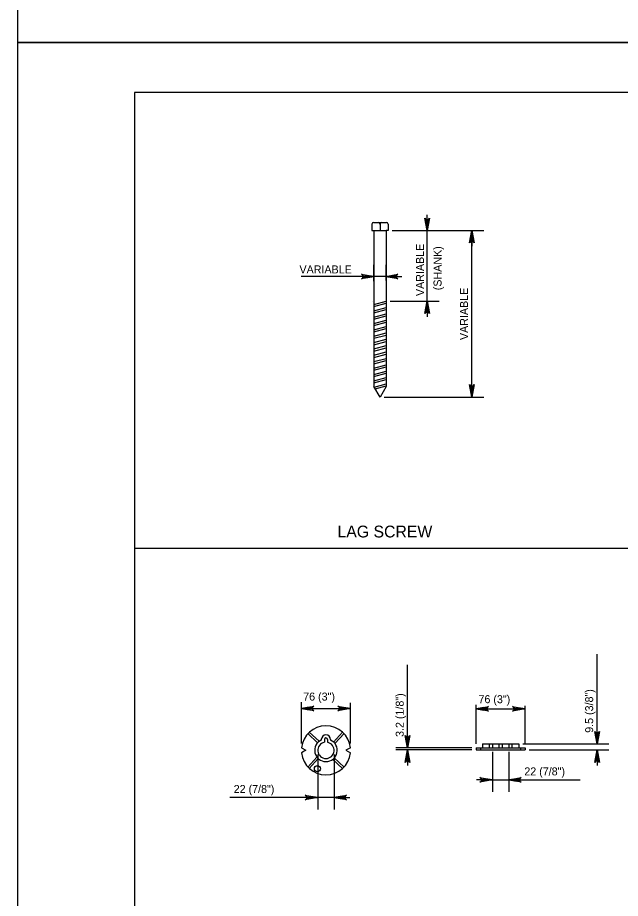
# Model space of a CAD drawing. Extents: x 0 to 36.3, y -66 to 0.
# Drawn here: x 0 to 9.04, y -56.84 to -43.62 of the extents above; entities that cross this region are included whole.
import ezdxf

# ---------------------------------------------------------------- set-up
doc = ezdxf.new("R2010")
doc.units = 0
for name, color, linetype in [('1', 7, 'Continuous'), ('3', 7, 'Continuous'), ('4', 7, 'Continuous'), ('5', 7, 'Continuous'), ('62', 7, 'Continuous'), ('63', 7, 'Continuous')]:
    doc.layers.add(name, color=color, linetype=linetype)

msp = doc.modelspace()

# ---------------------------------------------------------------- linework, layer by layer
at = {"layer": '1'}
msp.add_lwpolyline([(1.75, -65.25), (33.25, -65.25), (33.25, -44.75), (1.75, -44.75)], close=True, dxfattribs=at)
at = {"layer": '3'}
for p, q in [((5.617, -46.819), (6.989, -46.819)), ((6.811, -49.316), (6.811, -46.819)), ((6.811, -46.819), (6.811, -46.819)), ((6.811, -46.937), (6.811, -47.055)), ((5.34, -47.576), (5.34, -47.333)), ((5.525, -47.568), (5.525, -47.333)), ((5.222, -47.51), (4.252, -47.51)), ((5.525, -47.51), (5.34, -47.51)), ((5.643, -47.51), (5.761, -47.51)), ((5.494, -49.316), (6.989, -49.316)), ((1.75, -51.583), (32.25, -51.583)), ((8.687, -54.28), (8.687, -53.172)), ((5.847, -54.341), (5.847, -53.332)), ((4.254, -54.514), (4.254, -53.895)), ((4.373, -53.987), (4.87, -53.987)), ((4.989, -54.514), (4.989, -53.904)), ((4.989, -53.987), (4.989, -53.987)), ((6.873, -54.516), (6.873, -53.934)), ((6.991, -53.994), (7.489, -53.994)), ((7.607, -54.516), (7.607, -53.946)), ((7.607, -53.994), (7.607, -53.994)), ((8.687, -54.398), (8.687, -54.28)), ((5.847, -54.459), (5.847, -54.341)), ((7.573, -54.516), (8.864, -54.516)), ((8.687, -54.516), (8.687, -54.516)), ((4.499, -54.676), (4.499, -55.501)), ((4.745, -54.676), (4.745, -55.501)), ((6.811, -54.578), (5.67, -54.578)), ((6.811, -54.608), (5.67, -54.608)), ((5.847, -54.578), (5.847, -54.578)), ((7.117, -54.639), (7.117, -55.236)), ((7.363, -54.639), (7.363, -55.236)), ((7.668, -54.608), (8.864, -54.608)), ((5.847, -54.726), (5.847, -54.844)), ((8.687, -54.726), (8.687, -54.844)), ((6.998, -55.059), (6.88, -55.059)), ((7.117, -55.059), (8.432, -55.059)), ((7.363, -55.059), (7.363, -55.059)), ((7.481, -55.059), (7.599, -55.059)), ((4.745, -55.324), (3.181, -55.324)), ((4.38, -55.324), (4.447, -55.324)), ((4.863, -55.324), (4.981, -55.324))]:
    msp.add_line(p, q, dxfattribs=at)
for points in [[(6.14, -46.819), (6.105, -46.632), (6.115, -46.647), (6.128, -46.654), (6.14, -46.656), (6.153, -46.654), (6.165, -46.647), (6.175, -46.632), (6.14, -46.819), (6.165, -46.647), (6.153, -46.654), (6.14, -46.819), (6.14, -46.656), (6.128, -46.654), (6.14, -46.819), (6.115, -46.647)], [(6.811, -46.819), (6.846, -47.005), (6.836, -46.991), (6.824, -46.983), (6.811, -46.981), (6.799, -46.983), (6.786, -46.991), (6.776, -47.005), (6.811, -46.819), (6.786, -46.991), (6.799, -46.983), (6.811, -46.819), (6.811, -46.981), (6.824, -46.983), (6.811, -46.819), (6.836, -46.991)], [(5.34, -47.51), (5.154, -47.545), (5.168, -47.535), (5.175, -47.523), (5.178, -47.51), (5.175, -47.498), (5.168, -47.485), (5.154, -47.475), (5.34, -47.51), (5.168, -47.485), (5.175, -47.498), (5.34, -47.51), (5.178, -47.51), (5.175, -47.523), (5.34, -47.51), (5.168, -47.535)], [(5.514, -47.51), (5.701, -47.475), (5.686, -47.485), (5.679, -47.498), (5.677, -47.51), (5.679, -47.523), (5.686, -47.535), (5.701, -47.545), (5.514, -47.51), (5.686, -47.535), (5.679, -47.523), (5.514, -47.51), (5.677, -47.51), (5.679, -47.498), (5.514, -47.51), (5.686, -47.485)], [(6.14, -47.876), (6.175, -48.063), (6.165, -48.048), (6.153, -48.041), (6.14, -48.039), (6.128, -48.041), (6.115, -48.048), (6.105, -48.063), (6.14, -47.876), (6.115, -48.048), (6.128, -48.041), (6.14, -47.876), (6.14, -48.039), (6.153, -48.041), (6.14, -47.876), (6.165, -48.048)], [(6.811, -49.316), (6.776, -49.13), (6.786, -49.144), (6.799, -49.152), (6.811, -49.154), (6.824, -49.152), (6.836, -49.144), (6.846, -49.13), (6.811, -49.316), (6.836, -49.144), (6.824, -49.152), (6.811, -49.316), (6.811, -49.154), (6.799, -49.152), (6.811, -49.316), (6.786, -49.144)], [(4.255, -53.987), (4.441, -53.952), (4.427, -53.962), (4.419, -53.974), (4.417, -53.987), (4.419, -53.999), (4.427, -54.012), (4.441, -54.021), (4.255, -53.987), (4.427, -54.012), (4.419, -53.999), (4.255, -53.987), (4.417, -53.987), (4.419, -53.974), (4.255, -53.987), (4.427, -53.962)], [(4.989, -53.987), (4.802, -54.021), (4.817, -54.012), (4.824, -53.999), (4.826, -53.987), (4.824, -53.974), (4.817, -53.962), (4.802, -53.952), (4.989, -53.987), (4.817, -53.962), (4.824, -53.974), (4.989, -53.987), (4.826, -53.987), (4.824, -53.999), (4.989, -53.987), (4.817, -54.012)], [(6.873, -53.994), (7.059, -53.959), (7.045, -53.969), (7.037, -53.981), (7.035, -53.994), (7.037, -54.006), (7.045, -54.019), (7.059, -54.029), (6.873, -53.994), (7.045, -54.019), (7.037, -54.006), (6.873, -53.994), (7.035, -53.994), (7.037, -53.981), (6.873, -53.994), (7.045, -53.969)], [(7.607, -53.994), (7.42, -54.029), (7.435, -54.019), (7.442, -54.006), (7.444, -53.994), (7.442, -53.981), (7.435, -53.969), (7.42, -53.959), (7.607, -53.994), (7.435, -53.969), (7.442, -53.981), (7.607, -53.994), (7.444, -53.994), (7.442, -54.006), (7.607, -53.994), (7.435, -54.019)], [(5.847, -54.578), (5.812, -54.391), (5.822, -54.405), (5.835, -54.413), (5.847, -54.415), (5.86, -54.413), (5.872, -54.405), (5.882, -54.391), (5.847, -54.578), (5.872, -54.405), (5.86, -54.413), (5.847, -54.578), (5.847, -54.415), (5.835, -54.413), (5.847, -54.578), (5.822, -54.405)], [(8.687, -54.516), (8.652, -54.33), (8.662, -54.344), (8.674, -54.351), (8.687, -54.353), (8.699, -54.351), (8.712, -54.344), (8.722, -54.33), (8.687, -54.516), (8.712, -54.344), (8.699, -54.351), (8.687, -54.516), (8.687, -54.353), (8.674, -54.351), (8.687, -54.516), (8.662, -54.344)], [(5.847, -54.608), (5.882, -54.795), (5.872, -54.78), (5.86, -54.773), (5.847, -54.771), (5.835, -54.773), (5.822, -54.78), (5.812, -54.795), (5.847, -54.608), (5.822, -54.78), (5.835, -54.773), (5.847, -54.608), (5.847, -54.771), (5.86, -54.773), (5.847, -54.608), (5.872, -54.78)], [(8.687, -54.608), (8.722, -54.795), (8.712, -54.78), (8.699, -54.773), (8.687, -54.771), (8.674, -54.773), (8.662, -54.78), (8.652, -54.795), (8.687, -54.608), (8.662, -54.78), (8.674, -54.773), (8.687, -54.608), (8.687, -54.771), (8.699, -54.773), (8.687, -54.608), (8.712, -54.78)], [(7.117, -55.059), (6.93, -55.094), (6.944, -55.084), (6.952, -55.072), (6.954, -55.059), (6.952, -55.047), (6.944, -55.034), (6.93, -55.024), (7.117, -55.059), (6.944, -55.034), (6.952, -55.047), (7.117, -55.059), (6.954, -55.059), (6.952, -55.072), (7.117, -55.059), (6.944, -55.084)], [(7.363, -55.059), (7.549, -55.024), (7.535, -55.034), (7.527, -55.047), (7.525, -55.059), (7.527, -55.072), (7.535, -55.084), (7.549, -55.094), (7.363, -55.059), (7.535, -55.084), (7.527, -55.072), (7.363, -55.059), (7.525, -55.059), (7.527, -55.047), (7.363, -55.059), (7.535, -55.034)], [(4.499, -55.324), (4.312, -55.358), (4.327, -55.349), (4.334, -55.336), (4.336, -55.324), (4.334, -55.311), (4.327, -55.299), (4.312, -55.289), (4.499, -55.324), (4.327, -55.299), (4.334, -55.311), (4.499, -55.324), (4.336, -55.324), (4.334, -55.336), (4.499, -55.324), (4.327, -55.349)], [(4.745, -55.324), (4.931, -55.289), (4.917, -55.299), (4.909, -55.311), (4.907, -55.324), (4.909, -55.336), (4.917, -55.349), (4.931, -55.358), (4.745, -55.324), (4.917, -55.349), (4.909, -55.336), (4.745, -55.324), (4.907, -55.324), (4.909, -55.311), (4.745, -55.324), (4.917, -55.299)]]:
    msp.add_lwpolyline(points, dxfattribs=at)
for points in [[(6.831, -46.937), (6.792, -46.937), (6.811, -46.819)], [(5.222, -47.491), (5.222, -47.53), (5.34, -47.51)], [(5.643, -47.491), (5.643, -47.53), (5.525, -47.51)], [(6.831, -49.198), (6.792, -49.198), (6.811, -49.316)], [(4.373, -54.006), (4.373, -53.967), (4.255, -53.987)], [(4.87, -54.006), (4.87, -53.967), (4.989, -53.987)], [(6.991, -54.014), (6.991, -53.974), (6.873, -53.994)], [(7.489, -54.014), (7.489, -53.974), (7.607, -53.994)], [(8.707, -54.398), (8.667, -54.398), (8.687, -54.516)], [(5.867, -54.459), (5.828, -54.459), (5.847, -54.578)], [(5.867, -54.726), (5.828, -54.726), (5.847, -54.608)], [(8.707, -54.726), (8.667, -54.726), (8.687, -54.608)], [(6.998, -55.079), (6.998, -55.04), (7.117, -55.059)], [(7.481, -55.079), (7.481, -55.04), (7.363, -55.059)], [(4.38, -55.343), (4.38, -55.304), (4.499, -55.324)], [(4.863, -55.343), (4.863, -55.304), (4.745, -55.324)]]:
    msp.add_lwpolyline(points, close=True, dxfattribs=at)
at = {"layer": '4'}
for p, q in [((6.14, -46.701), (6.14, -46.583)), ((5.309, -46.723), (5.309, -46.819)), ((5.309, -46.723), (5.309, -46.723)), ((5.337, -46.696), (5.405, -46.696)), ((5.405, -46.696), (5.528, -46.696)), ((5.433, -46.723), (5.433, -46.819)), ((5.555, -46.723), (5.555, -46.819)), ((5.555, -46.723), (5.555, -46.723)), ((5.309, -46.819), (5.34, -46.819)), ((5.34, -46.819), (5.34, -47.865)), ((5.34, -46.819), (5.525, -46.819)), ((5.525, -46.819), (5.525, -47.865)), ((5.555, -46.819), (5.525, -46.819)), ((5.555, -46.819), (5.555, -46.819)), ((5.846, -46.819), (6.317, -46.819)), ((6.14, -47.876), (6.14, -46.819)), ((5.323, -47.884), (5.323, -47.884)), ((5.34, -47.865), (5.34, -49.157)), ((5.525, -47.865), (5.525, -49.157)), ((5.586, -47.876), (6.317, -47.876)), ((6.14, -47.994), (6.14, -48.112)), ((5.433, -49.316), (5.433, -49.316)), ((4.497, -54.5), (4.35, -54.364)), ((4.52, -54.479), (4.371, -54.341)), ((4.736, -54.49), (4.872, -54.343)), ((4.757, -54.513), (4.895, -54.364)), ((4.552, -54.453), (4.552, -54.46)), ((4.598, -54.453), (4.598, -54.494)), ((4.645, -54.453), (4.645, -54.494)), ((4.691, -54.453), (4.691, -54.46)), ((6.967, -54.516), (6.967, -54.578)), ((6.967, -54.516), (7.512, -54.516)), ((7.07, -54.516), (7.07, -54.578)), ((7.117, -54.516), (7.117, -54.578)), ((7.216, -54.516), (7.216, -54.578)), ((7.263, -54.516), (7.263, -54.578)), ((7.363, -54.516), (7.363, -54.578)), ((7.409, -54.516), (7.409, -54.578)), ((7.512, -54.516), (7.512, -54.578)), ((7.512, -54.516), (7.512, -54.516)), ((4.255, -54.576), (4.255, -54.576)), ((4.499, -54.614), (4.499, -54.614)), ((4.745, -54.614), (4.745, -54.614)), ((4.989, -54.576), (4.989, -54.576)), ((6.873, -54.578), (6.873, -54.608)), ((6.873, -54.578), (6.873, -54.578)), ((6.873, -54.578), (7.607, -54.578)), ((6.873, -54.608), (6.873, -54.608)), ((6.873, -54.608), (7.607, -54.608)), ((6.94, -54.578), (6.94, -54.608)), ((7.117, -54.578), (7.117, -54.578)), ((7.363, -54.578), (7.363, -54.578)), ((7.539, -54.578), (7.539, -54.608)), ((7.607, -54.578), (7.607, -54.608)), ((7.607, -54.578), (7.607, -54.578)), ((7.607, -54.608), (7.607, -54.608)), ((4.486, -54.716), (4.349, -54.865)), ((4.507, -54.739), (4.371, -54.886)), ((4.723, -54.75), (4.872, -54.888)), ((4.746, -54.729), (4.893, -54.865))]:
    msp.add_line(p, q, dxfattribs=at)
for points in [[(6.12, -46.701), (6.16, -46.701), (6.14, -46.819)], [(6.12, -47.994), (6.16, -47.994), (6.14, -47.876)]]:
    msp.add_lwpolyline(points, close=True, dxfattribs=at)
for points in [[(5.525, -49.157), (5.433, -49.316), (5.34, -49.157)], [(4.255, -54.576), (4.322, -54.614), (4.255, -54.653)], [(4.989, -54.576), (4.921, -54.614), (4.989, -54.653)]]:
    msp.add_lwpolyline(points, dxfattribs=at)
msp.add_circle((4.495, -54.892), 0.0461, dxfattribs=at)
for centre, radius, start, end in [((5.337, -46.723), 0.0272, 90, 180), ((5.405, -46.723), 0.0272, 0, 90), ((5.46, -46.723), 0.0272, 90, 180), ((5.528, -46.723), 0.0272, 0, 90), ((4.622, -54.615), 0.369, 6.0305, 173.9695), ((4.622, -54.453), 0.0692, 0, 180), ((4.622, -54.615), 0.169, 114.1477, 65.8523), ((4.622, -54.615), 0.123, 100.8069, 79.1931), ((4.622, -54.453), 0.0231, 0, 180), ((4.622, -54.615), 0.369, 186.0305, 353.9695)]:
    msp.add_arc(centre, radius, start, end, dxfattribs=at)
at = {"layer": '5'}
for p, q in [((5.34, -47.926), (5.525, -47.876)), ((5.34, -47.958), (5.525, -47.908)), ((5.34, -48.021), (5.525, -47.972)), ((5.34, -48.053), (5.525, -48.004)), ((5.34, -48.117), (5.525, -48.067)), ((5.34, -48.149), (5.525, -48.099)), ((5.34, -48.212), (5.525, -48.163)), ((5.34, -48.244), (5.525, -48.195)), ((5.34, -48.308), (5.525, -48.258)), ((5.34, -48.34), (5.525, -48.29)), ((5.34, -48.403), (5.525, -48.354)), ((5.34, -48.435), (5.525, -48.386)), ((5.34, -48.499), (5.525, -48.45)), ((5.34, -48.531), (5.525, -48.481)), ((5.34, -48.594), (5.525, -48.545)), ((5.34, -48.626), (5.525, -48.577)), ((5.34, -48.69), (5.525, -48.64)), ((5.34, -48.722), (5.525, -48.672)), ((5.34, -48.785), (5.525, -48.736)), ((5.34, -48.817), (5.525, -48.768)), ((5.34, -48.881), (5.525, -48.832)), ((5.34, -48.913), (5.525, -48.863)), ((5.34, -48.977), (5.525, -48.927)), ((5.34, -49.008), (5.525, -48.959)), ((5.34, -49.072), (5.525, -49.023)), ((5.34, -49.104), (5.525, -49.054)), ((5.346, -49.166), (5.525, -49.118)), ((5.362, -49.194), (5.525, -49.15))]:
    msp.add_line(p, q, dxfattribs=at)
at = {"layer": '62'}
msp.add_line((0, -44), (0, -44), dxfattribs=at)
at = {"layer": '63'}
for points in [[(0, -44), (34, -44), (34, -22), (0, -22)], [(0, -66), (34, -66), (34, -44), (0, -44)]]:
    msp.add_lwpolyline(points, close=True, dxfattribs=at)

# ---------------------------------------------------------------- texts
at = {"layer": '3'}
for s, height, p in [('VARIABLE', 0.12, (4.225, -47.462)), ('LAG SCREW', 0.1772, (4.795, -51.422)), ('76 (3")', 0.12, (4.281, -53.869)), ('76 (3")', 0.12, (6.909, -53.908))]:
    msp.add_text(s, height=height, dxfattribs=at).set_placement(p)
for s, p in [('VARIABLE', (6.752, -48.461)), ('9.5 (3/8")', (8.628, -54.352)), ('3.2 (1/8")', (5.788, -54.414))]:
    msp.add_text(s, height=0.12, rotation=90, dxfattribs=at).set_placement(p)
at = {"layer": '4'}
for s, p in [('VARIABLE', (6.092, -47.801)), ('(SHANK)', (6.355, -47.714))]:
    msp.add_text(s, height=0.12, rotation=90, dxfattribs=at).set_placement(p)
for p in [(7.596, -54.991), (3.239, -55.255)]:
    msp.add_text('22 (7/8")', height=0.12, dxfattribs=at).set_placement(p)

doc.saveas('drawing.dxf')
